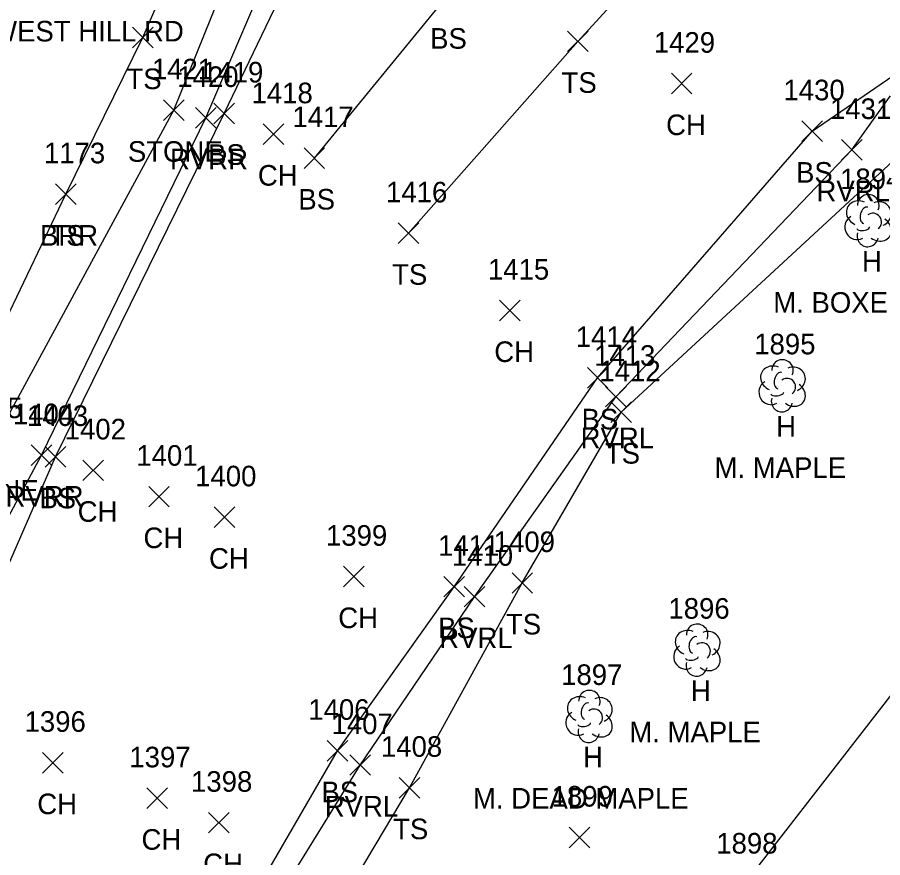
# Model space of a CAD drawing. Extents: x 1600395 to 1603269, y 874955 to 877143.
# Drawn here: x 1601724 to 1601808.1, y 875112.5 to 875194.1 of the extents above; entities that cross this region are included whole.
import ezdxf

# ---------------------------------------------------------------- set-up
doc = ezdxf.new("R2010")
doc.units = 0
for name, color, linetype in [('L_A', 7, 'Continuous'), ('L_C', 7, 'Continuous'), ('L_I', 7, 'Continuous'), ('L_TIC', 7, 'Continuous'), ('LABL', 7, 'Continuous'), ('LASF', 7, 'Continuous'), ('LAWE', 7, 'Continuous'), ('LELB', 7, 'Continuous'), ('LTD', 7, 'Continuous'), ('P_I', 7, 'Continuous'), ('PSU', 7, 'Continuous'), ('S_C', 7, 'Continuous')]:
    doc.layers.add(name, color=color, linetype=linetype)

msp = doc.modelspace()

# ---------------------------------------------------------------- linework, layer by layer
at = {"layer": 'L_TIC'}
for points in [[(1601735.226, 875191.128), (1601737.226, 875193.128)], [(1601737.226, 875191.128), (1601735.226, 875193.128)], [(1601777.499, 875190.764), (1601779.499, 875192.764)], [(1601779.499, 875190.764), (1601777.499, 875192.764)], [(1601777.499, 875190.764), (1601779.499, 875192.764)], [(1601779.499, 875190.764), (1601777.499, 875192.764)], [(1601787.578, 875186.66), (1601789.578, 875188.66)], [(1601789.578, 875186.66), (1601787.578, 875188.66)], [(1601738.232, 875184.072), (1601740.232, 875186.072)], [(1601740.232, 875184.072), (1601738.232, 875186.072)], [(1601741.355, 875183.332), (1601743.355, 875185.332)], [(1601743.355, 875183.332), (1601741.355, 875185.332)], [(1601743.118, 875183.771), (1601745.118, 875185.771)], [(1601745.118, 875183.771), (1601743.118, 875185.771)], [(1601747.916, 875181.754), (1601749.916, 875183.754)], [(1601749.916, 875181.754), (1601747.916, 875183.754)], [(1601800.249, 875182.04), (1601802.249, 875184.04)], [(1601802.249, 875182.04), (1601800.249, 875184.04)], [(1601804.115, 875180.224), (1601806.115, 875182.224)], [(1601806.115, 875180.224), (1601804.115, 875182.224)], [(1601751.894, 875179.432), (1601753.894, 875181.432)], [(1601753.894, 875179.432), (1601751.894, 875181.432)], [(1601727.745, 875175.922), (1601729.745, 875177.922)], [(1601729.745, 875175.922), (1601727.745, 875177.922)], [(1601727.745, 875175.922), (1601729.745, 875177.922)], [(1601729.745, 875175.922), (1601727.745, 875177.922)], [(1601761.039, 875172.128), (1601763.039, 875174.128)], [(1601763.039, 875172.128), (1601761.039, 875174.128)], [(1601770.886, 875164.628), (1601772.886, 875166.628)], [(1601772.886, 875164.628), (1601770.886, 875166.628)], [(1601779.415, 875158.083), (1601781.415, 875160.083)], [(1601781.415, 875158.083), (1601779.415, 875160.083)], [(1601781.196, 875156.26), (1601783.196, 875158.26)], [(1601783.196, 875156.26), (1601781.196, 875158.26)], [(1601781.711, 875154.76), (1601783.711, 875156.76)], [(1601783.711, 875154.76), (1601781.711, 875156.76)], [(1601725.379, 875150.584), (1601727.379, 875152.584)], [(1601727.379, 875150.584), (1601725.379, 875152.584)], [(1601726.736, 875150.414), (1601728.736, 875152.414)], [(1601728.736, 875150.414), (1601726.736, 875152.414)], [(1601730.408, 875149.11), (1601732.408, 875151.11)], [(1601732.408, 875149.11), (1601730.408, 875151.11)], [(1601736.802, 875146.554), (1601738.802, 875148.554)], [(1601738.802, 875146.554), (1601736.802, 875148.554)], [(1601743.17, 875144.554), (1601745.17, 875146.554)], [(1601745.17, 875144.554), (1601743.17, 875146.554)], [(1601755.724, 875138.788), (1601757.724, 875140.788)], [(1601757.724, 875138.788), (1601755.724, 875140.788)], [(1601772.099, 875138.171), (1601774.099, 875140.171)], [(1601774.099, 875138.171), (1601772.099, 875140.171)], [(1601765.475, 875137.812), (1601767.475, 875139.812)], [(1601767.475, 875137.812), (1601765.475, 875139.812)], [(1601767.463, 875136.841), (1601769.463, 875138.841)], [(1601769.463, 875136.841), (1601767.463, 875138.841)], [(1601754.131, 875121.883), (1601756.131, 875123.883)], [(1601756.131, 875121.883), (1601754.131, 875123.883)], [(1601726.486, 875120.718), (1601728.486, 875122.718)], [(1601728.486, 875120.718), (1601726.486, 875122.718)], [(1601756.337, 875120.493), (1601758.337, 875122.493)], [(1601758.337, 875120.493), (1601756.337, 875122.493)], [(1601761.135, 875118.29), (1601763.135, 875120.29)], [(1601763.135, 875118.29), (1601761.135, 875120.29)], [(1601736.612, 875117.266), (1601738.612, 875119.266)], [(1601738.612, 875117.266), (1601736.612, 875119.266)], [(1601742.607, 875114.898), (1601744.607, 875116.898)], [(1601744.607, 875114.898), (1601742.607, 875116.898)], [(1601777.65, 875113.457), (1601779.65, 875115.457)], [(1601779.65, 875113.457), (1601777.65, 875115.457)]]:
    msp.add_lwpolyline(points, dxfattribs=at)
at = {"layer": 'LABL'}
msp.add_lwpolyline([(1601678.037, 875019.801), (1601687.212, 875055.982), (1601695.924, 875094.108), (1601706.335, 875127.39), (1601719.177, 875156.975), (1601728.745, 875176.922)], dxfattribs=at)
at = {"layer": 'LASF'}
msp.add_lwpolyline([(1601712.321, 875125.386), (1601721.351, 875152.173), (1601739.232, 875185.072), (1601750.285, 875212.478), (1601747.91, 875211.652)], dxfattribs=at)
at = {"layer": 'LAWE'}
for points in [[(1601691.608, 874961.829), (1601690.191, 874993.063), (1601689.233, 875017.016), (1601693.176, 875046.242), (1601698.322, 875069.371), (1601704.726, 875096.639), (1601712.321, 875125.386), (1601726.379, 875151.584), (1601742.355, 875184.332), (1601749.838, 875201.821), (1601757.17, 875214.811), (1601763.474, 875228.289), (1601769.619, 875241.931), (1601778.226, 875255.274), (1601780.685, 875261.68), (1601794.383, 875288.119), (1601816.126, 875319.133), (1601836.101, 875339.545), (1601856.898, 875374.373), (1601871.663, 875400.698), (1601886.602, 875430.708)], [(1601739.843, 875093.177), (1601757.337, 875121.493), (1601768.463, 875137.841), (1601782.196, 875157.26), (1601805.115, 875181.224), (1601811.363, 875189.98), (1601818.624, 875191.892), (1601823.213, 875192.812), (1601844.145, 875211.079), (1601861.587, 875229.673), (1601864.028, 875235.309), (1601870.344, 875255.068), (1601872.905, 875271.961), (1601871.033, 875274.538), (1601876.566, 875297.895), (1601887.708, 875330.048), (1601901.388, 875359.117), (1601917.879, 875393.303), (1601921.976, 875399.296), (1601926.726, 875398.957), (1601927.656, 875400.898), (1601926.508, 875404.409), (1601936.606, 875427.424)]]:
    msp.add_lwpolyline(points, dxfattribs=at)
at = {"layer": 'LELB'}
for points in [[(1601752.894, 875180.432), (1601765.7, 875196.049), (1601797.293, 875217.933), (1601828.35, 875244.201), (1601846.179, 875266.657), (1601853.219, 875271.798), (1601862.325, 875276.828), (1601870.716, 875282.068)], [(1601778.499, 875191.764), (1601801.962, 875217.41), (1601831.73, 875242.445), (1601843.263, 875253.567), (1601849.805, 875259.324)], [(1601728.745, 875176.922), (1601736.226, 875192.128), (1601739.706, 875200.12), (1601744.296, 875211.427)], [(1601699.549, 874960.018), (1601694.142, 874994.174), (1601691.323, 875016.49), (1601695.461, 875045.712), (1601700.163, 875068.941), (1601706.127, 875096.094), (1601716.306, 875125.249), (1601727.736, 875151.414), (1601744.118, 875184.771), (1601751.843, 875200.822), (1601755.991, 875200.418)], [(1601762.039, 875173.128), (1601778.499, 875191.764)], [(1601727.077, 874960.561), (1601728.142, 874994.468), (1601727.416, 875015.008), (1601727.587, 875043.323), (1601731.608, 875066.074), (1601737.893, 875093.047), (1601755.131, 875122.883), (1601766.475, 875138.812), (1601780.415, 875159.083), (1601801.249, 875183.04), (1601811.363, 875189.98)], [(1601745.445, 875091.27), (1601762.135, 875119.29), (1601773.099, 875139.171), (1601782.711, 875155.76), (1601813.338, 875184.041)]]:
    msp.add_lwpolyline(points, dxfattribs=at)
at = {"layer": 'LTD'}
for p, q in [((1601806.668, 875174.412), (1601806.668, 875174.412)), ((1601806.668, 875174.412), (1601806.668, 875174.412)), ((1601798.325, 875158.372), (1601798.325, 875158.372)), ((1601798.325, 875158.372), (1601798.325, 875158.372)), ((1601790.044, 875132.701), (1601790.044, 875132.701)), ((1601790.044, 875132.701), (1601790.044, 875132.701)), ((1601779.564, 875126.264), (1601779.564, 875126.264)), ((1601779.564, 875126.264), (1601779.564, 875126.264))]:
    msp.add_line(p, q, dxfattribs=at)
for centre in [(1601806.715, 875175.846), (1601798.372, 875159.806), (1601790.091, 875134.135), (1601779.611, 875127.698)]:
    msp.add_arc(centre, 1.047, 335.52715, 180.95627, dxfattribs=at)
for centre, major_axis, ratio, start_param, end_param in [((1601805.876, 875175.079), (1.21, -0.512), 0.895232, 1.570796, 4.712389), ((1601807.71, 875174.996), (-1.141, -0.483), 0.949671, 1.570796, 4.712389), ((1601806.46, 875174.87), (-0.208, -0.792), 0.645439, 3.141593, 6.283185), ((1601805.585, 875173.703), (0.584, -1.042), 0.959034, 3.141593, 6.283185), ((1601807.168, 875174.245), (-0.5, 0.667), 0.989748, 3.141593, 6.283185), ((1601807.668, 875173.579), (-1.09, 0.792), 0.841452, 1.570796, 4.712389), ((1601806.21, 875173.662), (-0.625, -0.083), 0.423636, 0, 3.141593), ((1601806.668, 875172.912), (0.265, 1.061), 0.942809, 1.570796, 4.712389), ((1601797.533, 875159.038), (1.21, -0.512), 0.895232, 1.570796, 4.712389), ((1601799.366, 875158.955), (-1.141, -0.483), 0.949671, 1.570796, 4.712389), ((1601798.116, 875158.83), (-0.208, -0.792), 0.645439, 3.141593, 6.283185), ((1601797.242, 875157.663), (0.584, -1.042), 0.959034, 3.141593, 6.283185), ((1601798.825, 875158.205), (-0.5, 0.667), 0.989748, 3.141593, 6.283185), ((1601799.325, 875157.539), (-1.09, 0.792), 0.841452, 1.570796, 4.712389), ((1601797.867, 875157.622), (-0.625, -0.083), 0.423636, 0, 3.141593), ((1601798.325, 875156.872), (0.265, 1.061), 0.942809, 1.570796, 4.712389), ((1601789.252, 875133.367), (1.21, -0.512), 0.895232, 1.570796, 4.712389), ((1601791.086, 875133.284), (-1.141, -0.483), 0.949671, 1.570796, 4.712389), ((1601789.836, 875133.159), (-0.208, -0.792), 0.645439, 3.141593, 6.283185), ((1601790.544, 875132.534), (-0.5, 0.667), 0.989748, 3.141593, 6.283185), ((1601788.961, 875131.992), (0.584, -1.042), 0.959034, 3.141593, 6.283185), ((1601791.044, 875131.868), (-1.09, 0.792), 0.841452, 1.570796, 4.712389), ((1601789.586, 875131.951), (-0.625, -0.083), 0.423636, 0, 3.141593), ((1601790.044, 875131.201), (0.265, 1.061), 0.942809, 1.570796, 4.712389), ((1601778.772, 875126.931), (1.21, -0.512), 0.895232, 1.570796, 4.712389), ((1601780.605, 875126.848), (-1.141, -0.483), 0.949671, 1.570796, 4.712389), ((1601779.355, 875126.723), (-0.208, -0.792), 0.645439, 3.141593, 6.283185), ((1601778.481, 875125.556), (0.584, -1.042), 0.959034, 3.141593, 6.283185), ((1601780.064, 875126.098), (-0.5, 0.667), 0.989748, 3.141593, 6.283185), ((1601780.564, 875125.431), (-1.09, 0.792), 0.841452, 1.570796, 4.712389), ((1601779.564, 875124.764), (0.265, 1.061), 0.942809, 1.570796, 4.712389), ((1601779.106, 875125.514), (-0.625, -0.083), 0.423636, 0, 3.141593)]:
    msp.add_ellipse(centre, major_axis=major_axis, ratio=ratio, start_param=start_param, end_param=end_param, dxfattribs=at)
at = {"layer": 'PSU'}
msp.add_lwpolyline([(1601863.919, 875170.533), (1601833.603, 875145.136), (1601813.054, 875133.631), (1601794.635, 875109.895), (1601781.483, 875081.205), (1601775.908, 875056.872), (1601772.452, 875035.366)], dxfattribs=at)

# ---------------------------------------------------------------- texts
at = {"layer": 'L_A'}
for s, p in [('BS', (1601764.141, 875191.049)), ('TS', (1601734.636, 875187.128)), ('TS', (1601776.909, 875186.764)), ('TS', (1601776.909, 875186.764)), ('CH', (1601787.067, 875182.66)), ('STONE', (1601734.775, 875180.072)), ('RVRR', (1601738.867, 875179.332)), ('BS', (1601742.559, 875179.771)), ('CH', (1601747.405, 875177.754)), ('BS', (1601799.69, 875178.04)), ('RVRL', (1601801.682, 875176.224)), ('BS', (1601751.335, 875175.432)), ('BRR', (1601726.234, 875171.922)), ('TS', (1601727.155, 875171.922)), ('H', (1601806.101, 875169.412)), ('TS', (1601760.449, 875168.128)), ('CH', (1601770.374, 875160.628)), ('BS', (1601778.856, 875154.083)), ('H', (1601797.758, 875153.372)), ('RVRL', (1601778.763, 875152.26)), ('TS', (1601781.121, 875150.76)), ('STONE', (1601716.895, 875147.173)), ('RVRR', (1601722.891, 875146.584)), ('BS', (1601726.177, 875146.414)), ('CH', (1601729.896, 875145.11)), ('CH', (1601736.29, 875142.554)), ('CH', (1601742.658, 875140.554)), ('CH', (1601755.212, 875134.788)), ('BS', (1601764.916, 875133.812)), ('TS', (1601771.509, 875134.171)), ('RVRL', (1601765.03, 875132.841)), ('H', (1601789.477, 875127.701)), ('H', (1601778.997, 875121.264)), ('BS', (1601753.572, 875117.883)), ('CH', (1601725.974, 875116.718)), ('RVRL', (1601753.904, 875116.493)), ('TS', (1601760.545, 875114.29)), ('CH', (1601736.1, 875113.266)), ('CH', (1601742.095, 875110.898))]:
    msp.add_text(s, height=2, dxfattribs=at).set_placement(p)
at = {"layer": 'L_C'}
for s, p in [('M. BOXELDER', (1601797.479, 875165.412)), ('M. MAPLE', (1601791.774, 875149.372)), ('M. MAPLE', (1601783.493, 875123.701)), ('M. DEAD MAPLE', (1601768.304, 875117.264))]:
    msp.add_text(s, height=2, dxfattribs=at).set_placement(p)
at = {"layer": 'L_I'}
for s, p in [('1429', (1601785.878, 875190.66)), ('1421', (1601737.106, 875188.072)), ('1419', (1601741.984, 875187.771)), ('1420', (1601739.576, 875187.332)), ('1430', (1601798.47, 875186.04)), ('1418', (1601746.791, 875185.754)), ('1431', (1601802.989, 875184.224)), ('1417', (1601750.768, 875183.432)), ('1173', (1601726.62, 875179.922)), ('1173', (1601726.62, 875179.922)), ('1894', (1601803.975, 875177.412)), ('1416', (1601759.859, 875176.128)), ('1415', (1601769.76, 875168.628)), ('1414', (1601778.29, 875162.083)), ('1895', (1601795.632, 875161.372)), ('1413', (1601780.07, 875160.26)), ('1412', (1601780.586, 875158.76)), ('1405', (1601718.58, 875155.173)), ('1404', (1601723.608, 875154.584)), ('1403', (1601724.965, 875154.414)), ('1402', (1601728.637, 875153.11)), ('1401', (1601735.597, 875150.554)), ('1400', (1601741.312, 875148.554)), ('1399', (1601754.023, 875142.788)), ('1409', (1601770.32, 875142.171)), ('1411', (1601764.916, 875141.812)), ('1410', (1601766.25, 875140.841)), ('1896', (1601787.296, 875135.701)), ('1897', (1601776.871, 875129.264)), ('1406', (1601752.305, 875125.883)), ('1396', (1601724.738, 875124.718)), ('1407', (1601754.565, 875124.493)), ('1408', (1601759.364, 875122.29)), ('1397', (1601734.919, 875121.266)), ('1398', (1601740.914, 875118.898)), ('1899', (1601775.95, 875117.457))]:
    msp.add_text(s, height=2, dxfattribs=at).set_placement(p)
at = {"layer": 'P_I'}
msp.add_text('1898', height=2, dxfattribs=at).set_placement((1601791.943, 875112.895))
at = {"layer": 'S_C'}
msp.add_text('WEST HILL RD', height=2, dxfattribs=at).set_placement((1601721.485, 875191.753))

doc.saveas('drawing.dxf')
